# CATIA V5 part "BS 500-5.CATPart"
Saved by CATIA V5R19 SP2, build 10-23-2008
Part number: BS 500-5
Bounding box of the stored display mesh (mm): x -18.951 to 18.951, y -18.952 to 18.952, z 0 to 40
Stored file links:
  C:\Users\Bora\Desktop\BS\BS 500\BS 500-5.CATPart
  C:\Program Files\Dassault Systemes\B19\intel_a\reffiles\standard\MetricThickPitch.txt
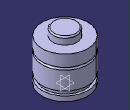
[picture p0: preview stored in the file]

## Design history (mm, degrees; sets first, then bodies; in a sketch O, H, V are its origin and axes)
Body1 (main body)
  Sketch1 on yz-plane, origin (0, 0, 0), H (0, 1, 0), V (0, 0, 1)
    point P1 (10, 39)
    point P3 (10, 39)
    point P5 (19, 24.5)
    point P6 (19, 22.5)
    point P9 (19, 24.5)
    point P14 (19, 22.5)
    line L1 (10, 39) -> (10, 34)
    arc A1 centre (9, 39) radius 1 from (10, 39) to (9, 40) ccw
    arc A2 centre (19, 23.5) radius 1 from (19, 24.5) to (19, 22.5) ccw
    line L2 (19, 0) -> (19, 4)
    line L3 (19, 24.5) -> (19, 34)
    line L4 (17, 7.5) -> (17, 4)
    line L5 (19, 7.5) -> (19, 22.5)
    line L6 (0, 40) -> (9, 40)
    point P15 (0, 40)
    line L7 (10, 34) -> (19, 34)
    line L8 (0, 0) -> (19, 0)
    line L9 (17, 7.5) -> (19, 7.5)
    line L10 (17, 4) -> (19, 4)
    coincidence: P15 V, P1 P3, P5 P9, P6 P14
    horizontal: L6 H, L7 H, L8 H, L9 H, L10 H
  Shaft1: profile Sketch1, axis Sketch1.V, angle 360
  Sketch2 on face of Shaft1 from Sketch1.L8, origin (0, 0, 0), H (1, 0, 0), V (0, -1, 0)
    point P1 (0, 0)
  Hole1: placed by Sketch2, at (0, 0, 0) direction (0, 0, 1), diameter 6.647, depth 4, threaded "M8", thread diameter 8, thread depth 4, pitch 1.25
